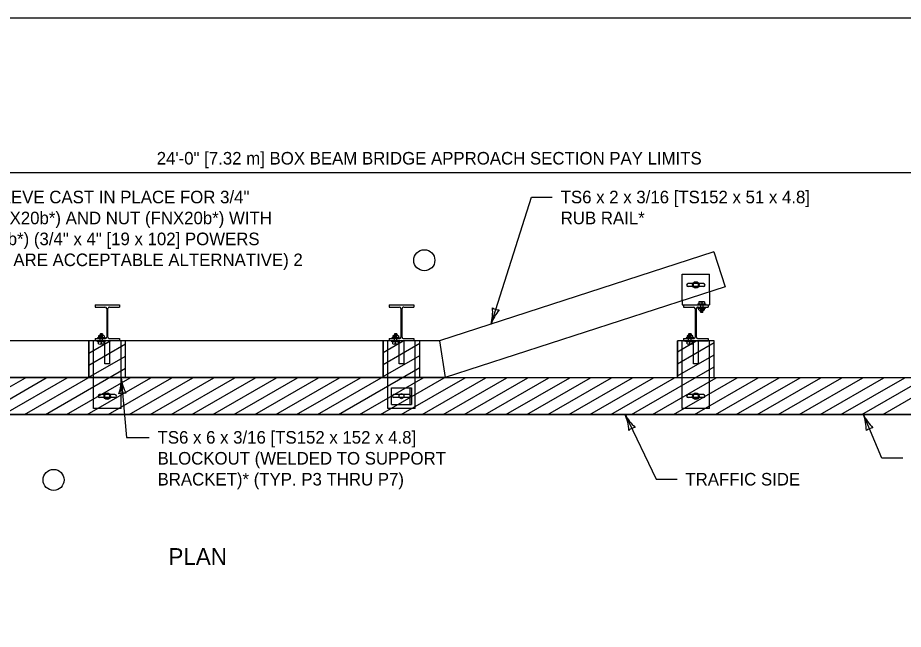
# Model space of a CAD drawing. Extents: x 49983 to 50021, y 49963.5 to 50011.4.
# Drawn here: x 50007.107 to 50011.337, y 49996.079 to 49998.999 of the extents above; entities that cross this region are included whole.
import ezdxf

# ---------------------------------------------------------------- set-up
doc = ezdxf.new("R2010")
doc.units = 0
for name, color, linetype in [('Level 1', 7, 'Continuous'), ('Level 10', 7, 'Continuous'), ('Level 2', 7, 'Continuous'), ('Level 3', 7, 'Continuous')]:
    doc.layers.add(name, color=color, linetype=linetype)

msp = doc.modelspace()

# ---------------------------------------------------------------- linework, layer by layer
at = {"layer": 'Level 1'}
for p, q in [((50010.4322, 49997.8817), (50009.122, 49997.456)), ((50010.4322, 49997.8817), (50010.4865, 49997.7146)), ((50010.4865, 49997.7146), (50009.1498, 49997.2803)), ((50010.3353, 49997.7294), (50010.3465, 49997.7357)), ((50010.3353, 49997.7165), (50010.3353, 49997.7294)), ((50010.3465, 49997.7102), (50010.3353, 49997.7165)), ((50010.3465, 49997.7357), (50010.3575, 49997.7294)), ((50010.3575, 49997.7165), (50010.3465, 49997.7102)), ((50010.3575, 49997.7294), (50010.3575, 49997.7165)), ((50010.412, 49997.6904), (50010.412, 49997.6277)), ((50010.2803, 49997.6476), (50010.2803, 49997.6277)), ((50007.4765, 49997.6277), (50007.5936, 49997.6277)), ((50007.4765, 49997.6277), (50007.4765, 49997.6167)), ((50007.4765, 49997.6167), (50007.5242, 49997.6167)), ((50007.5323, 49997.6098), (50007.5323, 49997.4735)), ((50007.5378, 49997.4734), (50007.5378, 49997.6098)), ((50007.5459, 49997.6167), (50007.5936, 49997.6167)), ((50007.5936, 49997.6277), (50007.5936, 49997.6167)), ((50008.882, 49997.6277), (50008.9992, 49997.6277)), ((50008.882, 49997.6277), (50008.882, 49997.6167)), ((50008.882, 49997.6167), (50008.9298, 49997.6167)), ((50008.9378, 49997.6098), (50008.9378, 49997.4735)), ((50008.9433, 49997.4734), (50008.9433, 49997.6098)), ((50008.9515, 49997.6167), (50008.9992, 49997.6167)), ((50008.9992, 49997.6277), (50008.9992, 49997.6167)), ((50010.2803, 49997.6277), (50010.412, 49997.6277)), ((50010.2876, 49997.6277), (50010.2876, 49997.6167)), ((50010.2876, 49997.6167), (50010.3353, 49997.6167)), ((50010.3434, 49997.6098), (50010.3434, 49997.4735)), ((50010.3489, 49997.4734), (50010.3489, 49997.6098)), ((50010.3554, 49997.6123), (50010.3554, 49997.6166)), ((50010.3554, 49997.6123), (50010.3927, 49997.6123)), ((50010.357, 49997.6167), (50010.4047, 49997.6167)), ((50010.361, 49997.6037), (50010.361, 49997.6103)), ((50010.3676, 49997.6017), (50010.3807, 49997.6017)), ((50010.3681, 49997.5945), (50010.3681, 49997.6017)), ((50010.3803, 49997.5945), (50010.3681, 49997.5945)), ((50010.3681, 49997.5945), (50010.3693, 49997.5932)), ((50010.3693, 49997.5932), (50010.379, 49997.5932)), ((50010.3699, 49997.6), (50010.3784, 49997.6)), ((50010.3699, 49997.5987), (50010.3784, 49997.5987)), ((50010.3699, 49997.5975), (50010.3784, 49997.5975)), ((50010.3699, 49997.5963), (50010.3784, 49997.5963)), ((50010.3742, 49997.6103), (50010.3742, 49997.6037)), ((50010.3803, 49997.5945), (50010.379, 49997.5932)), ((50010.3803, 49997.5945), (50010.3803, 49997.6017)), ((50010.3873, 49997.6037), (50010.3873, 49997.6103)), ((50010.3927, 49997.6123), (50010.3927, 49997.6167)), ((50010.4047, 49997.6277), (50010.4047, 49997.6167)), ((50007.4765, 49997.4666), (50007.5242, 49997.4666)), ((50007.4765, 49997.4666), (50007.4765, 49997.456)), ((50007.5258, 49997.471), (50007.4885, 49997.471)), ((50007.4885, 49997.471), (50007.4885, 49997.4666)), ((50007.4939, 49997.4796), (50007.4939, 49997.473)), ((50007.5136, 49997.4816), (50007.5005, 49997.4816)), ((50007.5009, 49997.4888), (50007.5021, 49997.49)), ((50007.5009, 49997.4888), (50007.5131, 49997.4888)), ((50007.5009, 49997.4888), (50007.5009, 49997.4816)), ((50007.5119, 49997.49), (50007.5021, 49997.49)), ((50007.5113, 49997.487), (50007.5028, 49997.487)), ((50007.5113, 49997.4857), (50007.5028, 49997.4857)), ((50007.5113, 49997.4845), (50007.5028, 49997.4845)), ((50007.5113, 49997.4833), (50007.5028, 49997.4833)), ((50007.507, 49997.473), (50007.507, 49997.4796)), ((50007.5131, 49997.4888), (50007.5119, 49997.49)), ((50007.5131, 49997.4888), (50007.5131, 49997.4816)), ((50007.5201, 49997.4796), (50007.5201, 49997.473)), ((50007.5258, 49997.471), (50007.5258, 49997.4666)), ((50007.5457, 49997.4666), (50007.5936, 49997.4666)), ((50007.5936, 49997.4666), (50007.5936, 49997.456)), ((50008.882, 49997.4666), (50008.882, 49997.456)), ((50008.882, 49997.4666), (50008.9297, 49997.4666)), ((50008.9313, 49997.471), (50008.8941, 49997.471)), ((50008.8941, 49997.471), (50008.8941, 49997.4666)), ((50008.8994, 49997.4796), (50008.8994, 49997.473)), ((50008.9191, 49997.4816), (50008.906, 49997.4816)), ((50008.9065, 49997.4888), (50008.9077, 49997.49)), ((50008.9065, 49997.4888), (50008.9186, 49997.4888)), ((50008.9065, 49997.4888), (50008.9065, 49997.4816)), ((50008.9174, 49997.49), (50008.9077, 49997.49)), ((50008.9169, 49997.487), (50008.9083, 49997.487)), ((50008.9169, 49997.4857), (50008.9083, 49997.4857)), ((50008.9169, 49997.4845), (50008.9083, 49997.4845)), ((50008.9169, 49997.4833), (50008.9083, 49997.4833)), ((50008.9126, 49997.473), (50008.9126, 49997.4796)), ((50008.9186, 49997.4888), (50008.9174, 49997.49)), ((50008.9186, 49997.4888), (50008.9186, 49997.4816)), ((50008.9257, 49997.4796), (50008.9257, 49997.473)), ((50008.9313, 49997.471), (50008.9313, 49997.4666)), ((50008.9513, 49997.4666), (50008.9992, 49997.4666)), ((50008.9992, 49997.4666), (50008.9992, 49997.456)), ((50010.2876, 49997.4666), (50010.2876, 49997.4556)), ((50010.2876, 49997.4666), (50010.3353, 49997.4666)), ((50010.3369, 49997.471), (50010.2996, 49997.471)), ((50010.2996, 49997.471), (50010.2996, 49997.4666)), ((50010.305, 49997.4796), (50010.305, 49997.473)), ((50010.3247, 49997.4816), (50010.3115, 49997.4816)), ((50010.312, 49997.4888), (50010.3132, 49997.49)), ((50010.312, 49997.4888), (50010.3242, 49997.4888)), ((50010.312, 49997.4888), (50010.312, 49997.4816)), ((50010.323, 49997.49), (50010.3132, 49997.49)), ((50010.3224, 49997.487), (50010.3139, 49997.487)), ((50010.3224, 49997.4857), (50010.3139, 49997.4857)), ((50010.3224, 49997.4845), (50010.3139, 49997.4845)), ((50010.3224, 49997.4833), (50010.3139, 49997.4833)), ((50010.3181, 49997.473), (50010.3181, 49997.4796)), ((50010.3242, 49997.4888), (50010.323, 49997.49)), ((50010.3242, 49997.4888), (50010.3242, 49997.4816)), ((50010.3312, 49997.4796), (50010.3312, 49997.473)), ((50010.3369, 49997.471), (50010.3369, 49997.4666)), ((50010.3568, 49997.4666), (50010.4047, 49997.4666)), ((50010.4047, 49997.4666), (50010.4047, 49997.4556)), ((50010.4047, 49997.4666), (50010.4047, 49997.4556)), ((50009.122, 49997.456), (50005.1235, 49997.456)), ((50007.4472, 49997.2799), (50007.4472, 49997.456)), ((50007.4472, 49997.455), (50007.4489, 49997.456)), ((50007.4472, 49997.3973), (50007.5489, 49997.456)), ((50007.4472, 49997.3396), (50007.6229, 49997.441)), ((50007.6229, 49997.2799), (50007.6229, 49997.456)), ((50008.8527, 49997.2799), (50008.8527, 49997.456)), ((50008.8527, 49997.4005), (50008.9489, 49997.456)), ((50008.8527, 49997.3428), (50009.0284, 49997.4442)), ((50009.0284, 49997.2799), (50009.0284, 49997.456)), ((50009.122, 49997.456), (50009.1498, 49997.2803)), ((50009.122, 49997.456), (50009.1498, 49997.2803)), ((50009.1235, 49997.4565), (50009.1235, 49997.4565)), ((50010.2583, 49997.2799), (50010.2583, 49997.4556)), ((50010.434, 49997.4556), (50010.2583, 49997.4556)), ((50010.2583, 49997.4037), (50010.3482, 49997.4556)), ((50010.2583, 49997.346), (50010.434, 49997.4474)), ((50010.2876, 49997.4556), (50010.4047, 49997.4556)), ((50010.434, 49997.2799), (50010.434, 49997.4556)), ((50007.4472, 49997.2818), (50007.6229, 49997.3833)), ((50008.8527, 49997.285), (50009.0284, 49997.3865)), ((50010.2583, 49997.2882), (50010.434, 49997.3897)), ((50007.2396, 49997.1042), (50007.6229, 49997.3255)), ((50008.6396, 49997.1042), (50009.0284, 49997.3287)), ((50010.0396, 49997.1042), (50010.434, 49997.3319)), ((50009.1498, 49997.2803), (50005.1235, 49997.2803)), ((50013.5013, 49997.2799), (50006.3204, 49997.2799)), ((50006.8396, 49997.1042), (50007.1439, 49997.2799)), ((50006.9396, 49997.1042), (50007.2439, 49997.2799)), ((50007.0396, 49997.1042), (50007.3439, 49997.2799)), ((50007.1396, 49997.1042), (50007.4439, 49997.2799)), ((50007.3396, 49997.1042), (50007.6439, 49997.2799)), ((50007.4396, 49997.1042), (50007.7439, 49997.2799)), ((50007.4692, 49997.2799), (50007.4472, 49997.2799)), ((50007.6009, 49997.2799), (50007.4692, 49997.2799)), ((50007.5396, 49997.1042), (50007.8439, 49997.2799)), ((50007.6229, 49997.2799), (50007.6009, 49997.2799)), ((50007.6396, 49997.1042), (50007.9439, 49997.2799)), ((50007.7396, 49997.1042), (50008.0439, 49997.2799)), ((50007.8396, 49997.1042), (50008.1439, 49997.2799)), ((50007.9396, 49997.1042), (50008.2439, 49997.2799)), ((50008.0396, 49997.1042), (50008.3439, 49997.2799)), ((50008.1396, 49997.1042), (50008.4439, 49997.2799)), ((50008.2396, 49997.1042), (50008.5439, 49997.2799)), ((50008.3396, 49997.1042), (50008.6439, 49997.2799)), ((50008.4396, 49997.1042), (50008.7439, 49997.2799)), ((50008.5396, 49997.1042), (50008.8439, 49997.2799)), ((50008.7396, 49997.1042), (50009.0439, 49997.2799)), ((50008.8396, 49997.1042), (50009.1439, 49997.2799)), ((50008.8747, 49997.2799), (50008.8527, 49997.2799)), ((50009.0065, 49997.2799), (50008.8747, 49997.2799)), ((50008.9396, 49997.1042), (50009.2439, 49997.2799)), ((50009.0284, 49997.2799), (50009.0065, 49997.2799)), ((50009.0396, 49997.1042), (50009.3439, 49997.2799)), ((50009.1396, 49997.1042), (50009.4439, 49997.2799)), ((50009.2396, 49997.1042), (50009.5439, 49997.2799)), ((50009.3396, 49997.1042), (50009.6439, 49997.2799)), ((50009.4396, 49997.1042), (50009.7439, 49997.2799)), ((50009.5396, 49997.1042), (50009.8439, 49997.2799)), ((50009.6396, 49997.1042), (50009.9439, 49997.2799)), ((50009.7396, 49997.1042), (50010.0439, 49997.2799)), ((50009.8396, 49997.1042), (50010.1439, 49997.2799)), ((50009.9396, 49997.1042), (50010.2439, 49997.2799)), ((50010.1396, 49997.1042), (50010.4439, 49997.2799)), ((50010.2396, 49997.1042), (50010.5439, 49997.2799)), ((50010.2803, 49997.2799), (50010.2583, 49997.2799)), ((50010.412, 49997.2799), (50010.2803, 49997.2799)), ((50010.3396, 49997.1042), (50010.6439, 49997.2799)), ((50010.434, 49997.2799), (50010.412, 49997.2799)), ((50010.4396, 49997.1042), (50010.7439, 49997.2799)), ((50010.5396, 49997.1042), (50010.8439, 49997.2799)), ((50010.6396, 49997.1042), (50010.9439, 49997.2799)), ((50010.7396, 49997.1042), (50011.0439, 49997.2799)), ((50010.8396, 49997.1042), (50011.1439, 49997.2799)), ((50010.9396, 49997.1042), (50011.2439, 49997.2799)), ((50011.0396, 49997.1042), (50011.3439, 49997.2799)), ((50011.1396, 49997.1042), (50011.4439, 49997.2799)), ((50011.2396, 49997.1042), (50011.5439, 49997.2799)), ((50008.8927, 49997.2316), (50008.989, 49997.2316)), ((50008.8928, 49997.1525), (50008.8928, 49997.2316)), ((50008.9813, 49997.1525), (50008.9813, 49997.2316)), ((50008.9893, 49997.1525), (50008.9893, 49997.2316)), ((50007.524, 49997.1985), (50007.5353, 49997.2049)), ((50007.524, 49997.1857), (50007.524, 49997.1985)), ((50007.5353, 49997.1793), (50007.524, 49997.1857)), ((50007.5353, 49997.2049), (50007.5463, 49997.1985)), ((50007.5463, 49997.1857), (50007.5353, 49997.1793)), ((50007.5463, 49997.1985), (50007.5463, 49997.1857)), ((50008.9296, 49997.1985), (50008.9408, 49997.2049)), ((50008.9296, 49997.1857), (50008.9296, 49997.1985)), ((50008.9408, 49997.1793), (50008.9296, 49997.1857)), ((50008.9408, 49997.2049), (50008.9518, 49997.1985)), ((50008.9518, 49997.1857), (50008.9408, 49997.1793)), ((50008.9518, 49997.1985), (50008.9518, 49997.1857)), ((50010.3351, 49997.1985), (50010.3464, 49997.2049)), ((50010.3351, 49997.1857), (50010.3351, 49997.1985)), ((50010.3464, 49997.1793), (50010.3351, 49997.1857)), ((50010.3464, 49997.2049), (50010.3574, 49997.1985)), ((50010.3574, 49997.1857), (50010.3464, 49997.1793)), ((50010.3574, 49997.1985), (50010.3574, 49997.1857)), ((50008.8927, 49997.1525), (50008.989, 49997.1525)), ((50013.5013, 49997.1042), (50005.4468, 49997.1042))]:
    msp.add_line(p, q, dxfattribs=at)
msp.add_lwpolyline([(49999.3835, 49998.9992), (50016.7501, 49998.9992), (50016.7501, 49987.7988), (49999.3835, 49987.7988)], close=True, dxfattribs=at)
for points in [[(50006.7444, 49997.2799), (50006.3204, 49997.2799), (50006.3204, 49997.456), (50003.275, 49997.456), (50003.275, 49997.2799), (50003.2457, 49997.2799), (50002.2562, 49997.4473), (50002.2558, 49997.4447), (50002.2559, 49997.452), (50001.5623, 49997.4576), (50001.5622, 49997.4503), (50001.7737, 49997.3496), (50002.2274, 49997.2739), (50003.2457, 49997.1042), (50005.4468, 49997.1042), (50005.4633, 49997.1042), (50015.1856, 49997.1042), (50015.1855, 49997.1666), (50015.1344, 49997.1847), (50015.2365, 49997.2209), (50015.1855, 49997.239), (50015.1855, 49997.2799), (50012.5423, 49997.2799)], [(50007.6229, 49997.2799), (50007.6229, 49997.456), (50007.4472, 49997.456), (50007.4472, 49997.2799)], [(50009.0284, 49997.2799), (50009.0284, 49997.456), (50008.8527, 49997.456), (50008.8527, 49997.2799)], [(50010.434, 49997.2799), (50010.434, 49997.4556), (50010.2583, 49997.4556), (50010.2583, 49997.2799)], [(50007.4472, 49997.2799), (50006.9201, 49997.2799)], [(50008.8527, 49997.2799), (50007.6229, 49997.2799)], [(50010.2583, 49997.2799), (50009.0284, 49997.2799)], [(50012.3666, 49997.2799), (50010.434, 49997.2799)]]:
    msp.add_lwpolyline(points, dxfattribs=at)
for centre in [(50010.3463, 49997.7229), (50007.535, 49997.1921), (50010.3461, 49997.1921)]:
    msp.add_circle(centre, 0.0155, dxfattribs=at)
for centre, radius, start, end in [((50007.5248, 49997.6092), 0.00746, 4.5337, 94.5337), ((50007.5453, 49997.6092), 0.00752, 85.0809, 175.0809), ((50008.9304, 49997.6092), 0.00746, 4.5337, 94.5337), ((50008.9508, 49997.6092), 0.00752, 85.0809, 175.0809), ((50010.3359, 49997.6092), 0.00746, 4.5337, 94.5337), ((50010.3564, 49997.6092), 0.00752, 85.0809, 175.0809), ((50010.3676, 49997.6007), 0.0116, 55.616, 124.384), ((50010.3676, 49997.6133), 0.0116, 235.616, 304.384), ((50010.3807, 49997.6007), 0.0116, 55.616, 124.384), ((50010.3807, 49997.6133), 0.0116, 235.616, 304.384), ((50007.5005, 49997.47), 0.0116, 55.616, 124.384), ((50007.5005, 49997.4826), 0.0116, 235.616, 304.384), ((50007.5136, 49997.47), 0.0116, 55.616, 124.384), ((50007.5136, 49997.4826), 0.0116, 235.616, 304.384), ((50007.5247, 49997.4741), 0.00753, 265.5645, 355.5652), ((50007.5452, 49997.474), 0.00741, 184.3799, 274.3799), ((50008.906, 49997.47), 0.0116, 55.616, 124.384), ((50008.906, 49997.4826), 0.0116, 235.616, 304.384), ((50008.9191, 49997.47), 0.0116, 55.616, 124.384), ((50008.9191, 49997.4826), 0.0116, 235.616, 304.384), ((50008.9303, 49997.4741), 0.00753, 265.5645, 355.5652), ((50008.9507, 49997.474), 0.00741, 184.3799, 274.3799), ((50010.3115, 49997.47), 0.0116, 55.616, 124.384), ((50010.3115, 49997.4826), 0.0116, 235.616, 304.384), ((50010.3247, 49997.47), 0.0116, 55.616, 124.384), ((50010.3247, 49997.4826), 0.0116, 235.616, 304.384), ((50010.3358, 49997.4741), 0.00753, 265.5645, 355.5649), ((50010.3563, 49997.474), 0.00741, 184.3799, 274.3799)]:
    msp.add_arc(centre, radius, start, end, dxfattribs=at)
at = {"layer": 'Level 10'}
for p, q in [((50010.2803, 49997.6476), (50010.2803, 49997.7741)), ((50010.412, 49997.6904), (50010.412, 49997.7741)), ((50010.3829, 49997.7295), (50010.3097, 49997.7295)), ((50010.3829, 49997.7148), (50010.3097, 49997.7148)), ((50010.3554, 49997.632), (50010.3927, 49997.632)), ((50010.3554, 49997.632), (50010.3554, 49997.6277)), ((50010.361, 49997.6419), (50010.361, 49997.632)), ((50010.3676, 49997.6427), (50010.3807, 49997.6427)), ((50010.3681, 49997.632), (50010.3681, 49997.6017)), ((50010.3742, 49997.6419), (50010.3742, 49997.632)), ((50010.3803, 49997.632), (50010.3803, 49997.6017)), ((50010.3873, 49997.6419), (50010.3873, 49997.632)), ((50010.3927, 49997.632), (50010.3927, 49997.6277)), ((50007.5009, 49997.4512), (50007.5009, 49997.4816)), ((50007.5131, 49997.4512), (50007.5131, 49997.4816)), ((50008.9065, 49997.4512), (50008.9065, 49997.4816)), ((50008.9186, 49997.4512), (50008.9186, 49997.4816)), ((50010.312, 49997.4512), (50010.312, 49997.4816)), ((50010.3242, 49997.4512), (50010.3242, 49997.4816)), ((50007.4692, 49997.1335), (50007.4692, 49997.456)), ((50007.4885, 49997.4512), (50007.4885, 49997.4556)), ((50007.5258, 49997.4512), (50007.4885, 49997.4512)), ((50007.4939, 49997.4414), (50007.4939, 49997.4512)), ((50007.5136, 49997.4406), (50007.5005, 49997.4406)), ((50007.507, 49997.4414), (50007.507, 49997.4512)), ((50007.5201, 49997.4414), (50007.5201, 49997.4512)), ((50007.5241, 49997.3466), (50007.5241, 49997.456)), ((50007.5258, 49997.4512), (50007.5258, 49997.4556)), ((50007.546, 49997.456), (50007.546, 49997.3466)), ((50007.6009, 49997.1335), (50007.6009, 49997.456)), ((50008.8747, 49997.1335), (50008.8747, 49997.456)), ((50008.8941, 49997.4512), (50008.8941, 49997.4556)), ((50008.9313, 49997.4512), (50008.8941, 49997.4512)), ((50008.8994, 49997.4414), (50008.8994, 49997.4512)), ((50008.9191, 49997.4406), (50008.906, 49997.4406)), ((50008.9126, 49997.4414), (50008.9126, 49997.4512)), ((50008.9257, 49997.4414), (50008.9257, 49997.4512)), ((50008.9296, 49997.3466), (50008.9296, 49997.456)), ((50008.9313, 49997.4512), (50008.9313, 49997.4556)), ((50008.9516, 49997.456), (50008.9516, 49997.3466)), ((50009.0065, 49997.1335), (50009.0065, 49997.456)), ((50010.2803, 49997.1335), (50010.2803, 49997.4556)), ((50010.2996, 49997.4512), (50010.2996, 49997.4556)), ((50010.3369, 49997.4512), (50010.2996, 49997.4512)), ((50010.305, 49997.4414), (50010.305, 49997.4512)), ((50010.3247, 49997.4406), (50010.3115, 49997.4406)), ((50010.3181, 49997.4414), (50010.3181, 49997.4512)), ((50010.3312, 49997.4414), (50010.3312, 49997.4512)), ((50010.3352, 49997.3466), (50010.3352, 49997.4556)), ((50010.3369, 49997.4512), (50010.3369, 49997.4556)), ((50010.3571, 49997.4556), (50010.3571, 49997.3466)), ((50010.412, 49997.1335), (50010.412, 49997.4556)), ((50007.546, 49997.3466), (50007.5241, 49997.3466)), ((50008.9516, 49997.3466), (50008.9296, 49997.3466)), ((50010.3571, 49997.3466), (50010.3352, 49997.3466)), ((50007.4913, 49997.1921), (50007.4913, 49997.1921)), ((50007.5718, 49997.1994), (50007.4986, 49997.1994)), ((50007.5718, 49997.1848), (50007.4986, 49997.1848)), ((50007.5791, 49997.1921), (50007.5791, 49997.1921)), ((50008.8968, 49997.1921), (50008.8968, 49997.1921)), ((50008.9773, 49997.1994), (50008.9041, 49997.1994)), ((50008.9773, 49997.1848), (50008.9041, 49997.1848)), ((50008.9847, 49997.1921), (50008.9847, 49997.1921)), ((50010.3024, 49997.1921), (50010.3024, 49997.1921)), ((50010.3829, 49997.1994), (50010.3097, 49997.1994)), ((50010.3829, 49997.1848), (50010.3097, 49997.1848)), ((50010.3902, 49997.1921), (50010.3902, 49997.1921)), ((50007.6009, 49997.1335), (50007.4692, 49997.1335)), ((50009.0065, 49997.1335), (50008.8747, 49997.1335)), ((50010.412, 49997.1335), (50010.2803, 49997.1335))]:
    msp.add_line(p, q, dxfattribs=at)
msp.add_lwpolyline([(50010.2803, 49997.7741), (50010.412, 49997.7741)], dxfattribs=at)
for centre, radius, start, end in [((50010.3097, 49997.7221), 0.00731, 90, 270), ((50010.3829, 49997.7221), 0.00731, 270, 90), ((50010.3676, 49997.6151), 0.0276, 76.2307, 103.7693), ((50010.3807, 49997.6151), 0.0276, 76.2307, 103.7693), ((50007.5005, 49997.4682), 0.0276, 256.2307, 283.7693), ((50007.5136, 49997.4682), 0.0276, 256.2307, 283.7693), ((50008.906, 49997.4682), 0.0276, 256.2307, 283.7693), ((50008.9191, 49997.4682), 0.0276, 256.2307, 283.7693), ((50010.3115, 49997.4682), 0.0276, 256.2307, 283.7693), ((50010.3247, 49997.4682), 0.0276, 256.2307, 283.7693), ((50007.4986, 49997.1921), 0.00731, 90, 270), ((50007.5718, 49997.1921), 0.00731, 270, 90), ((50008.9041, 49997.1921), 0.00731, 90, 270), ((50008.9773, 49997.1921), 0.00731, 270, 90), ((50010.3097, 49997.1921), 0.00731, 90, 270), ((50010.3829, 49997.1921), 0.00731, 270, 90)]:
    msp.add_arc(centre, radius, start, end, dxfattribs=at)
at = {"layer": 'Level 2'}
for centre in [(50009.0494, 49997.8409), (50007.2786, 49996.792)]:
    msp.add_circle(centre, 0.0503, dxfattribs=at)
at = {"layer": 'Level 3'}
for p, q in [((50013.5096, 49998.2581), (50005.0789, 49998.2581)), ((50009.3683, 49997.536), (50009.5609, 49998.1429)), ((50009.5609, 49998.1429), (50009.6609, 49998.1429)), ((50007.6009, 49997.2799), (50007.6263, 49996.9952)), ((50010.0088, 49997.1042), (50010.1564, 49996.7952)), ((50007.6263, 49996.9952), (50007.7353, 49996.9952)), ((50010.1564, 49996.7952), (50010.2564, 49996.7952))]:
    msp.add_line(p, q, dxfattribs=at)
msp.add_lwpolyline([(50011.3349, 49996.8952), (50011.2349, 49996.8952), (50011.1467, 49997.1042)], dxfattribs=at)
for centre, radius, start, end in [((50009.143, 49997.5955), 0.233, 345.2186, 4.4684), ((50009.5773, 49997.4601), 0.2223, 139.8473, 160.0308), ((50009.4071, 49997.6582), 0.0548, 234.5301, 270.2525), ((50007.3789, 49997.2693), 0.2223, 342.5565, 2.74), ((50007.8317, 49997.3121), 0.233, 187.9278, 207.1776), ((50007.6123, 49997.1522), 0.0548, 77.2393, 112.9617), ((50009.8044, 49997.0168), 0.2223, 2.9738, 23.1573), ((50010.2139, 49997.2149), 0.233, 208.3451, 227.5949), ((50010.9385, 49997.0264), 0.2223, 0.3233, 20.5068), ((50011.3566, 49997.2053), 0.233, 205.6946, 224.9444), ((50010.0641, 49996.9885), 0.0548, 97.6566, 133.379), ((50011.1965, 49996.9861), 0.0548, 95.0061, 130.7285)]:
    msp.add_arc(centre, radius, start, end, dxfattribs=at)

# ---------------------------------------------------------------- texts
at = {"layer": 'Level 2'}
for s, height, p in [('24\'-0" [7.32 m] BOX BEAM BRIDGE APPROACH SECTION PAY LIMITS', 0.06, (50007.7713, 49998.2981)), ('1 1/2" [38] DIA. GALV. STANDARD PIPE SLEEVE CAST IN PLACE FOR 3/4" ', 0.06, (50005.4326, 49998.1129)), ('TS6 x 2 x 3/16 [TS152 x 51 x 4.8] ', 0.06, (50009.7009, 49998.1129)), ('DIA. [M20] HIGH STRENGTH HEX BOLT (FBX20b*) AND NUT (FNX20b*) WITH', 0.06, (50005.4326, 49998.0129)), ('RUB RAIL*', 0.06, (50009.7009, 49998.0129)), ('TWO HARDENED FLAT WASHERS (FWC20b*) (3/4" x 4" [19 x 102] POWERS', 0.06, (50005.4326, 49997.9129)), ('WEDGE BOLT OR EQUIVALENT ANCHORS ARE ACCEPTABLE ALTERNATIVE) 2', 0.06, (50005.4326, 49997.8129)), ('TS6 x 6 x 3/16 [TS152 x 152 x 4.8]', 0.06, (50007.7753, 49996.9652)), ('BLOCKOUT (WELDED TO SUPPORT ', 0.06, (50007.7753, 49996.8652)), ('BRACKET)* (TYP. P3 THRU P7)', 0.06, (50007.7753, 49996.7652)), ('TRAFFIC SIDE', 0.06, (50010.2964, 49996.7652)), ('PLAN', 0.08, (50007.8272, 49996.386))]:
    msp.add_text(s, height=height, dxfattribs=at).set_placement(p)

doc.saveas('drawing.dxf')
